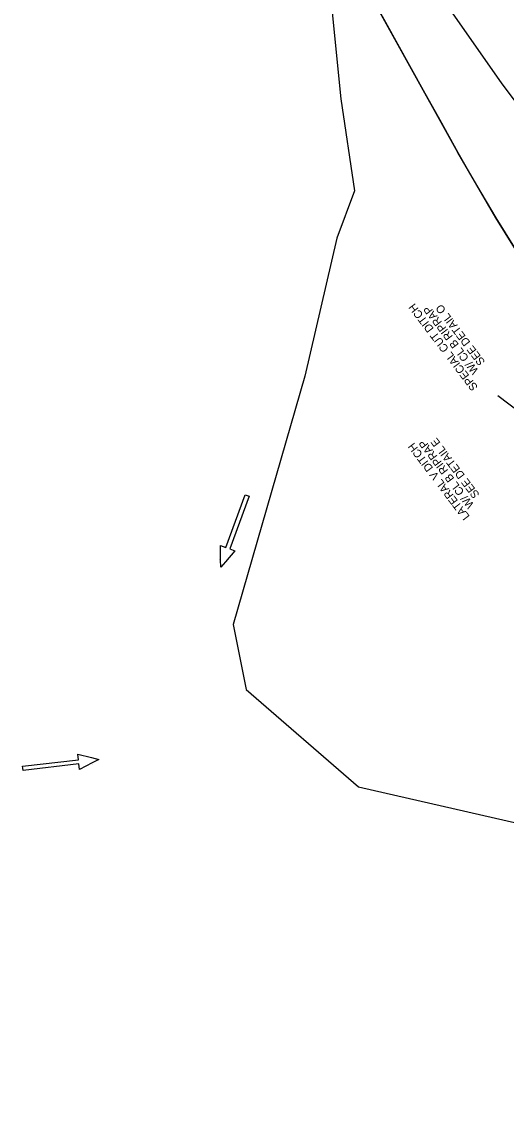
# Model space of a CAD drawing. Extents: x 465700 to 483515, y 488970 to 507540.
# Drawn here: x 475999 to 476301, y 500477 to 501162 of the extents above; entities that cross this region are included whole.
import ezdxf

# ---------------------------------------------------------------- set-up
doc = ezdxf.new("R2010")
doc.units = 0
for name, color, linetype in [('Default', 7, 'Continuous'), ('Exist Plan Preparation Drainage Flow Arrows', 7, 'Continuous'), ('Exist Plan Preparation Watershed Blue', 7, 'Continuous'), ('Prop Earthen Structure Head Ditch', 7, 'Continuous'), ('Prop Erosion Embankment Toe Protection Label', 7, 'Continuous')]:
    doc.layers.add(name, color=color, linetype=linetype)

# ---------------------------------------------------------------- blocks, each defined once
blk = doc.blocks.new('Existing ground flow arrow')
at = {"layer": 'Default'}
blk.add_line((2.5, -4.33), (2.5, -4.33), dxfattribs=at)
blk.add_lwpolyline([(-1.29, -47.2), (-1.28, -12.53), (-4.77, -12.53), (-1.65, -4.33), (0, 0), (1.65, -4.33), (4.78, -12.53), (1.28, -12.52), (1.29, -47.19), (0, -47.2)], close=True, dxfattribs=at)

msp = doc.modelspace()

# ---------------------------------------------------------------- linework, layer by layer
at = {"layer": 'Exist Plan Preparation Watershed Blue'}
for points in [[(476316.98, 501003.43), (476294.62, 501039.29), (476271.01, 501080.04), (476171.6, 501259.06)], [(476171.6, 501259.06), (476225.79, 501161.43), (476249.36, 501118.96), (476259.68, 501100.43), (476271.01, 501080.04), (476282.67, 501059.58), (476294.62, 501039.29), (476316.98, 501003.43)], [(476922.43, 500477.32), (476847.82, 500543.91), (476773.22, 500610.51), (476698.65, 500677.13), (476625.62, 500745.44), (476555.03, 500816.27), (476486.96, 500889.51), (476420.26, 500966.99), (476358.7, 501042.92), (476298.67, 501122.89), (476241.47, 501204.91)], [(476965.29, 500641), (476834.31, 500555.52), (476726.48, 500652.21), (476625.62, 500745.44), (476555.03, 500816.27), (476486.96, 500889.51), (476420.26, 500966.99), (476358.7, 501042.92), (476298.67, 501122.89), (476241.47, 501204.91)], [(476652.85, 501202.84), (476684.48, 501113.94), (476686.07, 501079.86), (476666.3, 501048.93), (476630.01, 501028.21), (476577.87, 501021.26), (476528.03, 501006.59), (476497.08, 501000.21), (476482.89, 500996.49), (476466.6, 500992.22), (476455.71, 500986.82), (476443.7, 500979.93), (476439.14, 500977.28), (476420.26, 500966.99), (476358.7, 501042.92), (476298.67, 501122.89), (476241.47, 501204.91)], [(476192.06, 501171.72), (476197.86, 501113.54), (476206.37, 501056.1), (476195.45, 501026.5), (476175.47, 500940.26), (476130.77, 500785.03), (476138.82, 500744.6), (476209, 500683.6), (476345.39, 500652.36)]]:
    msp.add_lwpolyline(points, dxfattribs=at)
at = {"layer": 'Prop Earthen Structure Head Ditch'}
msp.add_line((476338.32, 500895.56), (476295.96, 500928.06), dxfattribs=at)

# ---------------------------------------------------------------- block references
at = {"layer": 'Exist Plan Preparation Drainage Flow Arrows'}
for p, xscale, yscale, rotation in [((476122.91, 500820.84), 1.0124070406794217, 1.012407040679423, 159.76965421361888), ((476046.84, 500700.76), 1.012407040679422, 1.0124070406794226, -83.40036570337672)]:
    msp.add_blockref('Existing ground flow arrow', p, dxfattribs=dict(at, xscale=xscale, yscale=yscale, rotation=rotation))

# ---------------------------------------------------------------- texts
at = {"layer": 'Prop Erosion Embankment Toe Protection Label'}
for s, p in [('SPECIAL CUT DITCH', (476283.71, 500933.48)), ('W/ CL B RIPRAP', (476284.15, 500943.76)), ('SEE DETAIL O', (476288.2, 500949.26)), ('LATERAL V DITCH', (476278.62, 500852.66)), ('W/ CL B RIPRAP', (476281.28, 500860)), ('SEE DETAIL E', (476284.74, 500866.29))]:
    msp.add_text(s, height=5, rotation=127.10924, dxfattribs=at).set_placement(p)

doc.saveas('drawing.dxf')
